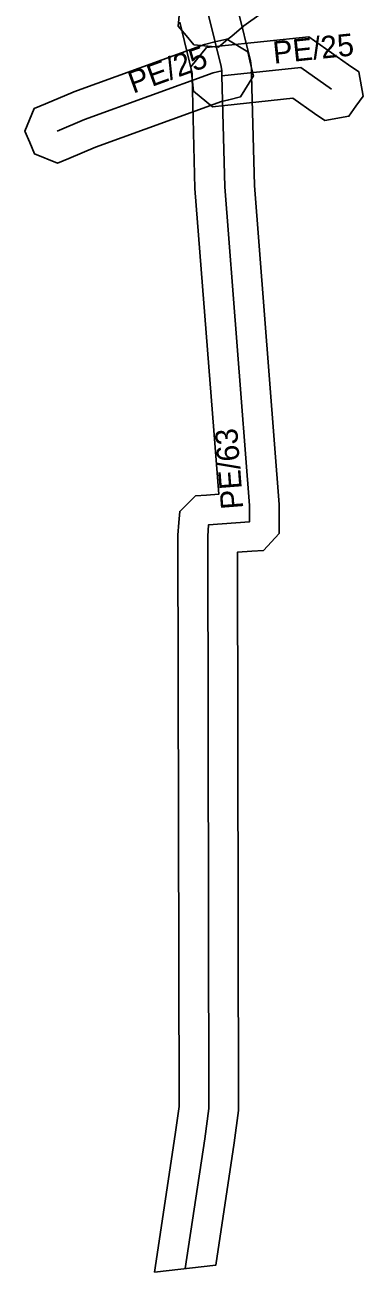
# Model space of a CAD drawing. Extents: x -783553 to -783321, y -1065190 to -1064961.
# Drawn here: x -783473.29 to -783461.92, y -1065189.88 to -1065147.89 of the extents above; entities that cross this region are included whole.
import ezdxf

# ---------------------------------------------------------------- set-up
doc = ezdxf.new("R2010")
doc.units = 0
for name, color, linetype in [('1', 7, 'Continuous'), ('30', 7, 'Continuous'), ('Plyn', 7, 'Continuous')]:
    doc.layers.add(name, color=color, linetype=linetype)

msp = doc.modelspace()

# ---------------------------------------------------------------- linework, layer by layer
at = {"layer": '1'}
for points in [[(-783466.118, -1065147.406), (-783465.706, -1065149.095), (-783465.672, -1065149.352), (-783465.666, -1065149.574), (-783465.571, -1065153.288), (-783464.732, -1065164.031), (-783464.732, -1065164.61), (-783464.732, -1065165.003), (-783465.267, -1065165.578), (-783465.659, -1065165.607), (-783466.14, -1065165.642), (-783466.101, -1065184.434), (-783466.25, -1065185.529), (-783466.871, -1065189.643), (-783468.928, -1065189.875), (-783468.23, -1065185.245), (-783468.101, -1065184.3), (-783468.141, -1065165.065), (-783468.109, -1065164.637), (-783468.081, -1065164.266), (-783467.556, -1065163.741), (-783467.185, -1065163.714), (-783466.765, -1065163.683), (-783467.569, -1065153.392), (-783467.666, -1065149.624), (-783467.668, -1065149.508), (-783467.674, -1065149.465), (-783468.082, -1065147.794)], [(-783465.34, -1065147.504), (-783465.926, -1065147.911), (-783466.333, -1065148.263), (-783466.46, -1065148.368), (-783466.778, -1065148.633), (-783467.603, -1065148.558), (-783467.868, -1065148.24), (-783468.133, -1065147.922), (-783468.058, -1065147.097)]]:
    msp.add_lwpolyline(points, dxfattribs=at)
for points in [[(-783467.182, -1065148.647), (-783466.77, -1065148.604), (-783463.743, -1065148.286), (-783462.4, -1065149.225), (-783462.06, -1065149.462), (-783461.916, -1065150.278), (-783462.153, -1065150.618), (-783462.39, -1065150.958), (-783463.206, -1065151.102), (-783463.546, -1065150.865), (-783464.277, -1065150.354), (-783466.562, -1065150.594), (-783466.974, -1065150.637), (-783467.618, -1065150.115), (-783467.661, -1065149.703), (-783467.704, -1065149.291)], [(-783466.671, -1065150.459), (-783470.917, -1065151.998), (-783471.814, -1065152.378), (-783472.195, -1065152.54), (-783472.963, -1065152.228), (-783473.125, -1065151.847), (-783473.287, -1065151.466), (-783472.975, -1065150.698), (-783472.594, -1065150.536), (-783471.671, -1065150.145), (-783471.641, -1065150.133), (-783467.249, -1065148.541), (-783466.905, -1065148.458), (-783466.502, -1065148.361), (-783465.795, -1065148.792), (-783465.698, -1065149.195), (-783465.601, -1065149.598), (-783466.032, -1065150.305), (-783466.435, -1065150.402)]]:
    msp.add_lwpolyline(points, close=True, dxfattribs=at)
at = {"layer": 'Plyn'}
for points in [[(-783467.899, -1065189.759), (-783467.24, -1065185.387), (-783467.101, -1065184.367), (-783467.141, -1065165.101), (-783467.112, -1065164.711), (-783465.732, -1065164.61), (-783465.732, -1065164.07), (-783466.57, -1065153.34), (-783466.666, -1065149.599), (-783466.67, -1065149.43), (-783466.69, -1065149.28), (-783467.1, -1065147.6), (-783468.35, -1065139.34), (-783469.73, -1065137.59)], [(-783466.67, -1065149.43), (-783466.96, -1065149.5), (-783471.285, -1065151.068), (-783471.29, -1065151.07), (-783472.204, -1065151.457)], [(-783466.666, -1065149.599), (-783464.01, -1065149.32), (-783462.973, -1065150.045)]]:
    msp.add_lwpolyline(points, dxfattribs=at)

# ---------------------------------------------------------------- texts
at = {"layer": '30'}
for s, rotation, p in [('PE/25', 5.9967, (-783464.909, -1065149.193)), ('PE/25', 19.9278, (-783469.651, -1065150.203)), ('PE/63', 94.4657, (-783465.94, -1065164.167))]:
    msp.add_text(s, height=0.75, rotation=rotation, dxfattribs=at).set_placement(p)

doc.saveas('drawing.dxf')
